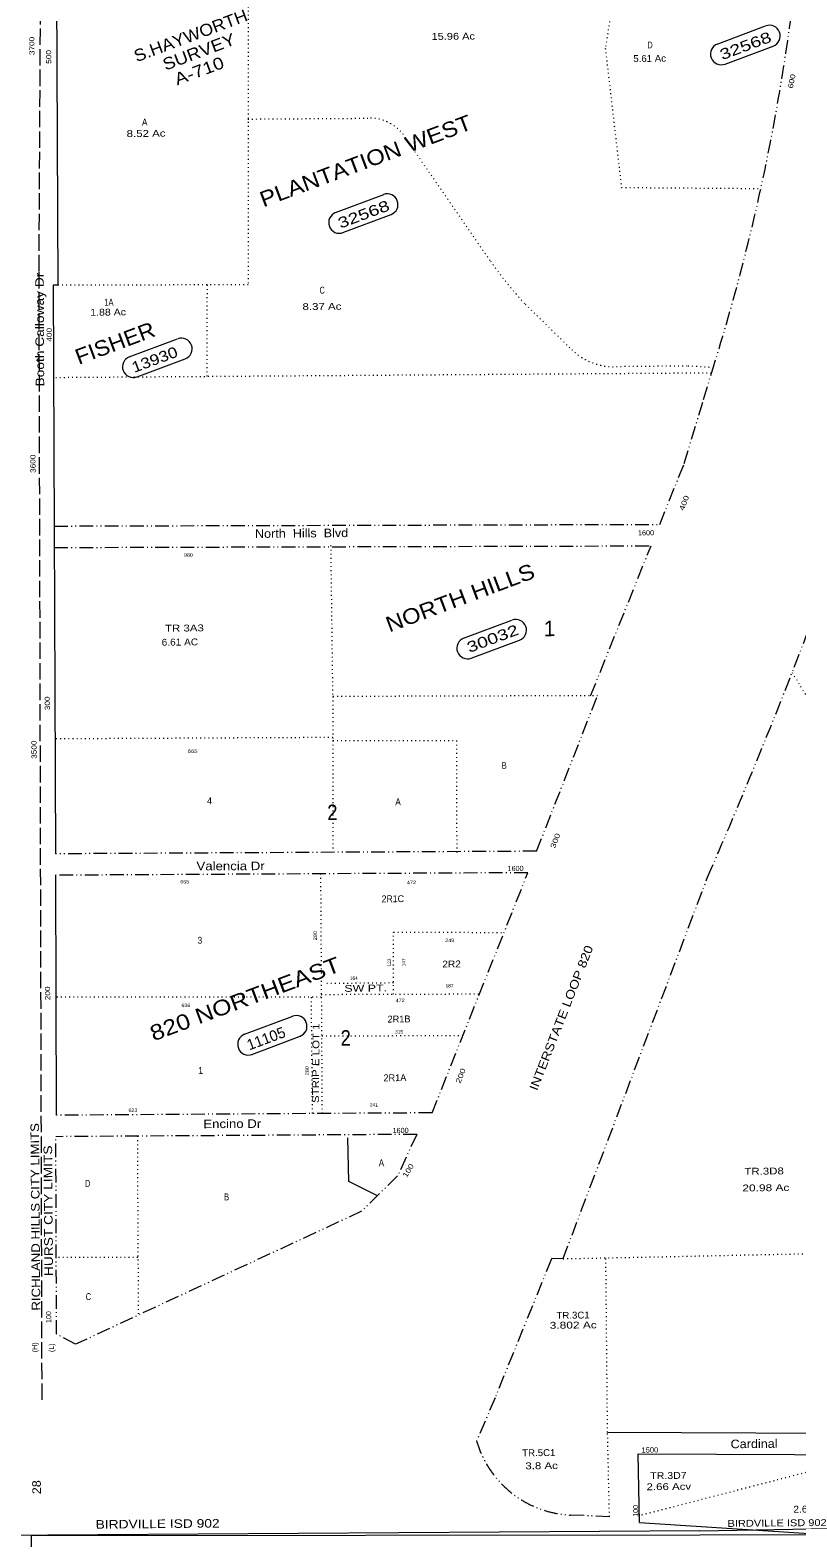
# Model space of a CAD drawing. Extents: x 2356373 to 2371954, y 6966197 to 6989612.
# Drawn here: x 2364359 to 2366146, y 6980551 to 6984068 of the extents above; entities that cross this region are included whole.
import ezdxf

# ---------------------------------------------------------------- set-up
doc = ezdxf.new("R2010")
doc.units = 0
doc.header["$LTSCALE"] = 6.4
for name, pattern in [('DASH_DOUBLE_DOT', [9.2, 5, -1.2, 0.3, -1.2, 0.3, -1.2]), ('DOTTED', [1.5, 0.3, -1.2]), ('LONG_DASHED', [7.5, 6, -1.5])]:
    doc.linetypes.add(name, pattern=pattern)
for name, color, linetype in [('10', 7, 'Continuous'), ('11', 7, 'Continuous'), ('18', 7, 'Continuous'), ('20', 7, 'Continuous'), ('21', 7, 'Continuous'), ('22', 7, 'Continuous'), ('24', 7, 'Continuous'), ('25', 7, 'Continuous'), ('26', 7, 'Continuous')]:
    doc.layers.add(name, color=color, linetype=linetype)
for name, color, linetype, lineweight in [('12', 7, 'Continuous', 13), ('15', 7, 'Continuous', 13), ('16', 7, 'DOTTED', 13), ('17', 7, 'Continuous', 13), ('19', 7, 'Continuous', 13), ('23', 7, 'Continuous', 13), ('27', 7, 'LONG_DASHED', 13), ('4', 7, 'Continuous', 13), ('5', 7, 'DOTTED', 13), ('6', 7, 'DOTTED', 13), ('9', 7, 'DOTTED', 13)]:
    doc.layers.add(name, color=color, linetype=linetype, lineweight=lineweight)

msp = doc.modelspace()

# ---------------------------------------------------------------- linework, layer by layer
at = {"layer": '15', "linetype": 'DASH_DOUBLE_DOT'}
for p, q in [((2365928.995, 6983205.949), (2365947.122, 6983267.78)), ((2365883.782, 6983056.865), (2365928.995, 6983205.949)), ((2365826.611, 6982914.891), (2365883.782, 6983056.865)), ((2364415.237, 6982910.956), (2365826.611, 6982914.891)), ((2364415.467, 6982860.981), (2365806.458, 6982864.856)), ((2365665.652, 6982515.167), (2365806.458, 6982864.856)), ((2365539.588, 6982152.534), (2365681.617, 6982515.213)), ((2365539.588, 6982152.534), (2364418.726, 6982146.493)), ((2365601.445, 6981202.356), (2365938.25, 6982092.268)), ((2365296.116, 6981542.415), (2364419.706, 6981536.756)), ((2365260.281, 6981492.206), (2364419.228, 6981486.775)), ((2364420.708, 6981026.642), (2364419.228, 6981486.775)), ((2365260.281, 6981492.206), (2365215.832, 6981395.466)), ((2365215.832, 6981395.466), (2365131.706, 6981312.851)), ((2365131.706, 6981312.851), (2364464.932, 6981002.584)), ((2365601.445, 6981202.356), (2365574.315, 6981201.612)), ((2364464.932, 6981002.584), (2364420.708, 6981026.642)), ((2365709.503, 6980600.349), (2365619.537, 6980604.331))]:
    msp.add_line(p, q, dxfattribs=at)
at = {"layer": '15'}
for p, q in [((2364418.238, 6982096.513), (2364419.706, 6981536.756)), ((2365705.039, 6980797.292), (2366500.131, 6980793.734)), ((2365779.795, 6980586.983), (2366237.835, 6980557.221))]:
    msp.add_line(p, q, dxfattribs=at)
for points in [[(2364401.114, 6984853.528), (2364408.272, 6984328.439), (2364420.301, 6984325.157), (2364423.673, 6983472.918), (2364412.679, 6983472.611), (2364418.726, 6982146.493)], [(2365779.795, 6980586.983), (2365776.163, 6980746.994), (2366687.842, 6980742.912)]]:
    msp.add_lwpolyline(points, dxfattribs=at)
at = {"layer": '15', "linetype": 'DASH_DOUBLE_DOT'}
for points in [[(2365296.116, 6981542.415), (2365519.395, 6982102.449), (2364418.238, 6982096.513)], [(2365574.315, 6981201.612), (2365442.898, 6980877.725), (2365399.892, 6980777.728)]]:
    msp.add_lwpolyline(points, dxfattribs=at)
for centre, radius, start, end in [((2361330.102, 6984734.687), 4844.449, 342.37406, 353.75276), ((2353890.048, 6987345.173), 13143.522, 336.44324, 339.37604), ((2365630.18, 6980843.974), 239.924, 196.04276, 267.47276)]:
    msp.add_arc(centre, radius, start, end, dxfattribs=at)
at = {"layer": '16'}
for p, q in [((2364771.577, 6983473.236), (2364423.673, 6983472.918)), ((2364771.577, 6983473.236), (2364770.788, 6983259.385)), ((2365947.122, 6983267.78), (2364413.659, 6983256.839)), ((2365064.884, 6982517.974), (2365060.459, 6982866.637)), ((2365681.617, 6982515.213), (2365064.929, 6982513.374)), ((2365064.929, 6982513.374), (2365064.939, 6982410.602)), ((2365064.868, 6982417.799), (2364417.073, 6982414.436)), ((2365601.374, 6981202.169), (2366365.891, 6981217.893)), ((2365705.039, 6980797.292), (2365701.042, 6981204.219)), ((2365709.503, 6980600.349), (2365705.039, 6980797.292))]:
    msp.add_line(p, q, dxfattribs=at)
msp.add_lwpolyline([(2366135.253, 6982569.426), (2366356.721, 6982202.31), (2366365.454, 6982141.632)], dxfattribs=at)
at = {"layer": '17'}
for p, q in [((2365960.738, 6984035.171), (2366073.293, 6984077.365)), ((2365979.193, 6983988.363), (2366090.75, 6984030.549)), ((2365070.837, 6983642.131), (2365183.394, 6983684.226)), ((2365088.293, 6983595.315), (2365200.849, 6983637.411)), ((2364590.27, 6983305.7), (2364702.827, 6983347.794)), ((2364608.726, 6983258.894), (2364720.283, 6983300.979)), ((2365369.51, 6982649.53), (2365482.066, 6982691.625)), ((2365386.966, 6982602.714), (2365499.523, 6982644.809)), ((2364858.723, 6981725.66), (2364971.279, 6981767.753)), ((2364876.179, 6981678.842), (2364988.735, 6981720.938))]:
    msp.add_line(p, q, dxfattribs=at)
for centre, start, end in [((2366082.521, 6984053.961), 290.56276, 110.56276), ((2365969.966, 6984011.767), 110.56276, 290.56276), ((2365191.622, 6983660.813), 290.56276, 110.56276), ((2365080.065, 6983618.728), 110.56276, 290.56276), ((2364712.055, 6983324.391), 290.56276, 110.56276), ((2364599.499, 6983282.297), 110.56276, 290.56276), ((2365491.294, 6982668.222), 290.56276, 110.56276), ((2365378.738, 6982626.128), 110.56276, 290.56276), ((2364979.508, 6981744.341), 290.56276, 110.56276), ((2364867.951, 6981702.256), 110.56276, 290.56276)]:
    msp.add_arc(centre, 24.992, start, end, dxfattribs=at)
at = {"layer": '23'}
for points in [[(2365919.906, 6980558.596), (2367013.599, 6980560.142), (2367014.163, 6980909.854)], [(2364379.886, 6978668.771), (2364362.344, 6980556.393), (2365919.906, 6980558.596)]]:
    msp.add_lwpolyline(points, dxfattribs=at)
at = {"layer": '27'}
for p, q in [((2364383.975, 6984359.392), (2364379.384, 6983503.475)), ((2364379.384, 6983503.475), (2364386.282, 6980867.347))]:
    msp.add_line(p, q, dxfattribs=at)
at = {"layer": '4'}
for q in [(2371917.244, 6980666.691), (2359921.814, 6980527.373)]:
    msp.add_line((2365919.817, 6980567.793), q, dxfattribs=at)
at = {"layer": '5'}
msp.add_line((2366325.251, 6980744.54), (2365779.44, 6980602.795), dxfattribs=at)
at = {"layer": '6'}
for p, q in [((2364866.946, 6984247.267), (2364867.551, 6983473.28)), ((2364866.751, 6983860.168), (2365146.657, 6983862.117)), ((2365234.084, 6983816.088), (2365432.196, 6983528.621)), ((2364867.551, 6983473.28), (2364771.577, 6983473.236)), ((2365512.906, 6983428.742), (2365621.493, 6983322.437)), ((2365064.939, 6982410.602), (2365064.55, 6982149.978)), ((2365036.089, 6982099.842), (2365039.592, 6981537.556)), ((2365037.889, 6981811.886), (2364418.994, 6981811.916)), ((2365013.896, 6981811.86), (2365016.591, 6981537.5)), ((2365037.843, 6981818.655), (2365406.712, 6981819.808)), ((2365367.731, 6981722.17), (2365038.451, 6981721.065)), ((2364609.155, 6981488), (2364611.226, 6981070.502)), ((2364609.904, 6981205.153), (2364419.958, 6981204.787))]:
    msp.add_line(p, q, dxfattribs=at)
for points in [[(2365750.492, 6984343.991), (2365699.836, 6984025.199), (2365737.395, 6983700.615), (2366062.382, 6983698.258)], [(2365952.045, 6983280.536), (2365890.675, 6983284.162), (2365720.778, 6983282.494)], [(2365064.939, 6982410.602), (2365352.862, 6982410.631), (2365353.453, 6982146.908)], [(2365205.912, 6981819.175), (2365206.492, 6981963.682), (2365463.908, 6981963.272)]]:
    msp.add_lwpolyline(points, dxfattribs=at)
at = {"layer": '6', "linetype": 'Continuous'}
msp.add_lwpolyline([(2365168.712, 6981348.946), (2365101.864, 6981382.089), (2365099.96, 6981484.264)], dxfattribs=at)
at = {"layer": '6'}
for centre, radius, start, end in [((2365151.612, 6983764.692), 97.498, 31.79376, 92.59776), ((2366197.646, 6984064.649), 934.476, 215.00276, 222.88276), ((2365719.402, 6983422.442), 139.956, 225.60662, 270.56276)]:
    msp.add_arc(centre, radius, start, end, dxfattribs=at)
at = {"layer": '9'}
msp.add_line((2365206.014, 6981845.338), (2365045.513, 6981843.763), dxfattribs=at)

# ---------------------------------------------------------------- texts
at = {"layer": '10'}
for s, width, p in [('TR 3A3', 1.25, (2364673.548, 6982664.589)), ('TR.3D8', 1.25, (2366023.872, 6981398.044)), ('TR.3C1', 1.05, (2365586.048, 6981062.081)), ('TR.5C1', 1.05, (2365506.221, 6980741.383)), ('TR.3D7', 1.15, (2365804.666, 6980688.131))]:
    msp.add_text(s, height=15.99, rotation=0.563, dxfattribs=dict(at, width=width)).set_placement(p)
at = {"layer": '11'}
for s, width, p in [('15.96 Ac', 1.2, (2365294.823, 6984044.725)), ('5.61 Ac', 1.05, (2365765.203, 6983993.259)), ('8.52 Ac', 1.25, (2364584.238, 6983818.203)), ('8.37 Ac', 1.25, (2364994.093, 6983414.638)), ('1.88 Ac', 1.15, (2364499.355, 6983401.482)), ('6.61 AC', 1.1, (2364665.872, 6982631.922)), ('20.98 Ac', 1.3, (2366019.254, 6981359.109)), ('3.802 Ac', 1.3, (2365570.282, 6981038.833)), ('3.8 Ac', 1.25, (2365513.517, 6980711.063)), ('2.66 Acv', 1.25, (2365795.921, 6980662.25)), ('2.661 AC', 1.1, (2366138.344, 6980609.929))]:
    msp.add_text(s, height=15.99, rotation=0.563, dxfattribs=dict(at, width=width)).set_placement(p)
at = {"layer": '12'}
for s, rotation, width, p in [('D', 0.563, 0.7, (2365797.883, 6984024.872)), ('A', 0.563, 0.9, (2364619.965, 6983845.048)), ('C', 0.563, 0.75, (2365033.706, 6983453.017)), ('1A', 0.563, 0.8, (2364532.115, 6983424.997)), ('B', 0.563, 0.75, (2365458.48, 6982344.786)), ('A', 0.563, 0.9, (2365210.381, 6982259.871)), ('2R1C', 0.563, 0.95, (2365178.614, 6982033.419)), ('3', 0.563, 0.9, (2364749.678, 6981936.832)), ('2R2', 0.563, 1.1, (2365320.071, 6981881.351)), (' SW PT.', 0.563, 1.35, (2365083.692, 6981824.544)), ('STRIP E LOT 1', 89.592, 1.25, (2365032.333, 6981565.227)), ('A', 0.563, 0.9, (2365171.664, 6981417.817)), ('D', 0.563, 0.7, (2364487.319, 6981369.806)), ('B', 0.563, 0.75, (2364811.541, 6981338.399)), ('C', 0.563, 0.75, (2364488.912, 6981105.791))]:
    msp.add_text(s, height=15.99, rotation=rotation, dxfattribs=dict(at, width=width)).set_placement(p)
for s, p in [('4', (2364771.476, 6982262.159)), ('2R1B', (2365192.366, 6981753.029)), ('1', (2364750.661, 6981633.121)), ('2R1A', (2365182.715, 6981615.972))]:
    msp.add_text(s, height=15.99, rotation=0.563, dxfattribs=at).set_placement(p)
at = {"layer": '17'}
for s, width, p in [('32568', 1.35, (2365972.107, 6983997.391)), ('32568', 1.35, (2365082.206, 6983604.354)), ('13930', 1.2, (2364601.639, 6983267.921)), ('30032', 1.35, (2365382.847, 6982614.872))]:
    msp.add_text(s, height=24.99, rotation=20.563, dxfattribs=dict(at, width=width)).set_placement(p)
msp.add_text('11105', height=24.99, rotation=20.563, dxfattribs=at).set_placement((2364870.093, 6981687.881))
at = {"layer": '18'}
for s, width, p in [('PLANTATION WEST', 1.15, (2364902.766, 6983654.077)), ('FISHER', 1.1, (2364472.489, 6983286.748)), ('NORTH HILLS', 1.15, (2365196.427, 6982662.727)), ('820 NORTHEAST', 1.2, (2364646.943, 6981709.082))]:
    msp.add_text(s, height=35.99, rotation=20.563, dxfattribs=dict(at, width=width)).set_placement(p)
at = {"layer": '19'}
for s, rotation, width, p in [('Booth Calloway Dr', 90.226, 1.2, (2364392.005, 6983236.37)), ('North  Hills  Blvd', 0.563, 1.1, (2364883.345, 6982883.192)), ('Valencia Dr', 0.143, 1.15, (2364746.997, 6982108.058)), ('INTERSTATE LOOP 820', 68.622, 1.2, (2365540.849, 6981592.696)), ('Encino Dr', 0.313, 1.15, (2364762.902, 6981506.626)), ('Cardinal', 0.563, 1.1, (2365991.908, 6980760.15))]:
    msp.add_text(s, height=19.99, rotation=rotation, dxfattribs=dict(at, width=width)).set_placement(p)
at = {"layer": '20'}
for s, width, p in [('S.HAYWORTH', 1.1, (2364607.518, 6983992.585)), ('SURVEY', 1.15, (2364674.693, 6983972.951)), ('A-710', 1.2, (2364702.025, 6983938.53))]:
    msp.add_text(s, height=27.99, rotation=20.563, dxfattribs=dict(at, width=width)).set_placement(p)
at = {"layer": '21', "width": 1.2}
for height, p in [(19.99, (2364512.119, 6980572.461)), (15.99, (2365984.712, 6980576.729))]:
    msp.add_text('BIRDVILLE ISD 902', height=height, rotation=0.563, dxfattribs=at).set_placement(p)
at = {"layer": '22'}
msp.add_text('1', height=35.99, rotation=0.563, dxfattribs=at).set_placement((2365556.417, 6982653.967))
at = {"layer": '22', "width": 0.9}
for p in [(2365051.764, 6982225.221), (2365082.925, 6981699.07)]:
    msp.add_text('2', height=35.99, rotation=0.563, dxfattribs=at).set_placement(p)
at = {"layer": '24'}
for s, height, rotation, width, p in [('3700', 12, 90.563, 1.2, (2364369.417, 6984009.342)), ('500', 12, 90.563, 1.2, (2364408.606, 6983989.132)), ('600', 11.99, 78.758, 1.25, (2366136.716, 6983930.926)), ('400', 12, 90.563, 1.2, (2364409.973, 6983341.019)), ('3600', 12, 90.563, 1.2, (2364371.991, 6983034.828)), ('400', 12, 68.944, 1.35, (2365882.463, 6982945.791)), ('1600', 12, 0.563, 1.05, (2365776.048, 6982889.161)), ('980', 7.997, 0.563, 1.15, (2364717.819, 6982839.378)), ('300', 12, 90.563, 1.2, (2364405.419, 6982481.503)), ('3500', 12, 90.563, 1.2, (2364374.541, 6982368.03)), ('300', 12, 68.944, 1.35, (2365582.283, 6982157.953)), ('1600', 12, 0.563, 1.05, (2365471.821, 6982106.181)), ('200', 12, 90.563, 1.2, (2364406.064, 6981805.09)), ('200', 12, 68.944, 1.35, (2365361.728, 6981609.732)), ('1600', 12, 0.563, 1.05, (2365203.896, 6981495.211)), ('100', 12, 58.875, 1.25, (2365236.916, 6981390.364)), ('1500', 12, 0.563, 1.1, (2365784.062, 6980750.01))]:
    msp.add_text(s, height=height, rotation=rotation, dxfattribs=dict(at, width=width)).set_placement(p)
for s, p in [('100', (2364408.461, 6981052.214)), ('(H)', (2364376.138, 6980984.115)), ('(L)', (2364415.124, 6980984.498)), ('100', (2365776.535, 6980600.277))]:
    msp.add_text(s, height=12, rotation=90.563, dxfattribs=at).set_placement(p)
at = {"layer": '25'}
for s, rotation, width, p in [(' 665', 0.563, 1.3, (2364722.314, 6982381.744)), ('665', 0.563, 1.15, (2364709.311, 6982077.097)), ('472', 0.563, 1.2, (2365237.184, 6982075.684)), ('280', 90.563, 1.2, (2365027.564, 6981945.059)), ('249', 0.563, 1.2, (2365326.485, 6981940.697)), ('636', 0.563, 1.15, (2364712.141, 6981788.902)), ('472', 0.563, 1.2, (2365210.895, 6981800.4)), ('280', 90.563, 1.2, (2365008.621, 6981630.157)), ('623', 0.563, 1.15, (2364588.577, 6981544.354))]:
    msp.add_text(s, height=7.997, rotation=rotation, dxfattribs=dict(at, width=width)).set_placement(p)
for s, rotation, p in [('123', 90.563, (2365200.078, 6981883.87)), ('147', 90.563, (2365234.065, 6981884.204)), ('164', 0.563, (2365104.412, 6981852.44)), ('187', 0.563, (2365327.527, 6981834.735)), ('315', 0.563, (2365209.855, 6981727.109)), ('241', 0.563, (2365151.303, 6981556.979))]:
    msp.add_text(s, height=7.997, rotation=rotation, dxfattribs=at).set_placement(p)
at = {"layer": '26'}
for s, rotation, width, p in [('RICHLAND HILLS CITY LIMITS', 90.415, 1.15, (2364383.066, 6981081.262)), ('HURST CITY LIMITS', 90.415, 1.2, (2364412.636, 6981161.695)), ('28', 90.563, 1.1, (2364384.39, 6980652.985))]:
    msp.add_text(s, height=19.99, rotation=rotation, dxfattribs=dict(at, width=width)).set_placement(p)

doc.saveas('drawing.dxf')
